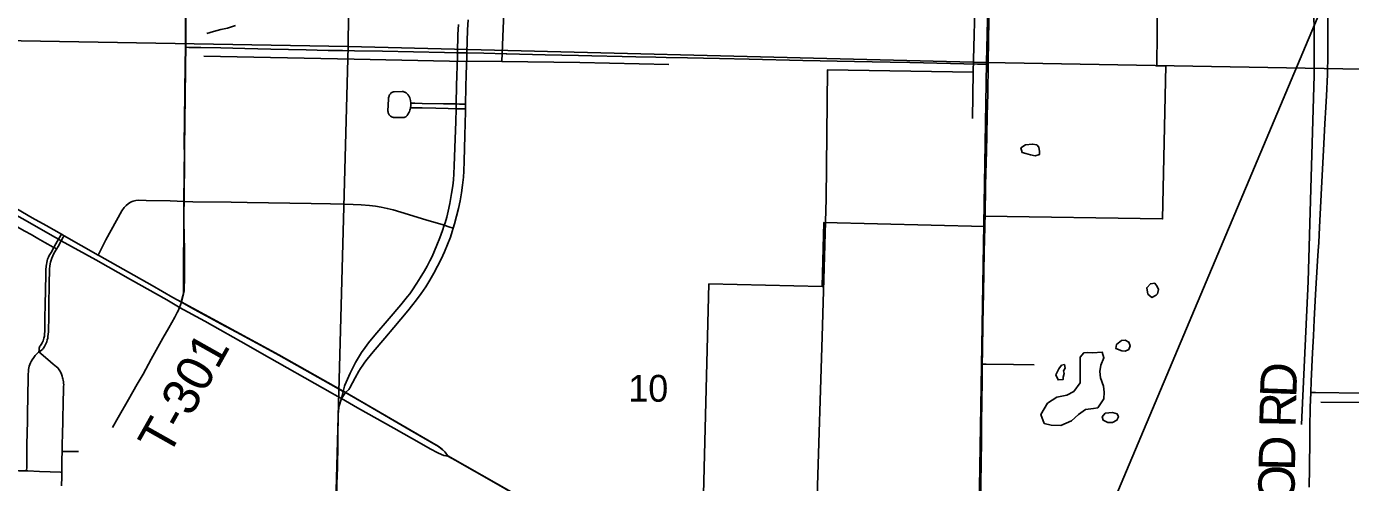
# Model space of a CAD drawing. Extents: x 0 to 34, y 0 to 22.
# Drawn here: x 4.977 to 7.043, y 16.271 to 16.982 of the extents above; entities that cross this region are included whole.
import ezdxf

# ---------------------------------------------------------------- set-up
doc = ezdxf.new("R2010")
doc.units = 0
for name, color, linetype in [('GM_X_City_Street', 7, 'Continuous'), ('GM_X_Corporation', 7, 'Continuous'), ('GM_X_County_Road', 7, 'Continuous'), ('GM_X_Minor_Lake', 7, 'Continuous'), ('GM_X_Minor_River', 7, 'Continuous'), ('GM_X_Rail_Line', 7, 'Continuous'), ('GM_X_Section_Text', 7, 'Continuous'), ('GM_X_Township_Road', 7, 'Continuous'), ('GM_X_Township_Road_Text', 7, 'Continuous'), ('GM_X_US_Route', 7, 'Continuous')]:
    doc.layers.add(name, color=color, linetype=linetype)

msp = doc.modelspace()

# ---------------------------------------------------------------- linework, layer by layer
at = {"layer": 'GM_X_City_Street'}
for points in [[(5.5759, 16.8557), (5.5763, 16.8589), (5.5763, 16.8609), (5.5763, 16.863), (5.5758, 16.8667), (5.5752, 16.8689), (5.5746, 16.8711), (5.5738, 16.8731), (5.5732, 16.8741), (5.5723, 16.8755), (5.5716, 16.8764), (5.5705, 16.8775), (5.5697, 16.8783), (5.5689, 16.8789), (5.5682, 16.8793), (5.5674, 16.8798), (5.5663, 16.8802), (5.5653, 16.8805), (5.5642, 16.8808), (5.563, 16.8809), (5.5503, 16.8807), (5.5491, 16.8805), (5.548, 16.8802), (5.5473, 16.8799), (5.5465, 16.8795), (5.5458, 16.879), (5.5453, 16.8784), (5.5445, 16.8776), (5.5439, 16.8769), (5.5432, 16.8759), (5.5427, 16.875), (5.5423, 16.8739), (5.5419, 16.8728), (5.5416, 16.8713), (5.5414, 16.8694), (5.5407, 16.8502), (5.5408, 16.8491), (5.5411, 16.8479), (5.5415, 16.8468), (5.5421, 16.8456), (5.5426, 16.8448), (5.5431, 16.8442), (5.5438, 16.8433), (5.5447, 16.8425), (5.5457, 16.8418), (5.547, 16.8412), (5.5481, 16.8407), (5.5493, 16.8404), (5.5506, 16.8402), (5.5645, 16.8402), (5.5659, 16.8405), (5.567, 16.8409), (5.5683, 16.8416), (5.5694, 16.8425), (5.5704, 16.8436), (5.5713, 16.8447), (5.5722, 16.846), (5.5729, 16.8473), (5.5735, 16.8486), (5.5742, 16.85), (5.5747, 16.8517), (5.5753, 16.8535), (5.5759, 16.8557)], [(5.5763, 16.863), (5.5825, 16.8629), (5.5941, 16.8625), (5.6273, 16.8618), (5.6471, 16.8615), (5.6522, 16.8614), (5.6618, 16.8613)], [(5.5759, 16.8557), (5.5835, 16.8557), (5.5939, 16.8556), (5.6153, 16.855), (5.6344, 16.8545), (5.6469, 16.8542), (5.6532, 16.8541), (5.6616, 16.8539)], [(5.2224, 16.7092), (5.2364, 16.7091), (5.2958, 16.7083), (5.3207, 16.7079), (5.4206, 16.7062), (5.4509, 16.7056), (5.4727, 16.7051), (5.4865, 16.7045), (5.4991, 16.704), (5.5116, 16.7031), (5.521, 16.702), (5.5303, 16.7005), (5.5395, 16.6985), (5.5487, 16.6963), (5.5607, 16.6928), (5.5997, 16.681), (5.6267, 16.6728), (5.6285, 16.6722), (5.6357, 16.67), (5.6426, 16.6679)]]:
    msp.add_lwpolyline(points, dxfattribs=at)
at = {"layer": 'GM_X_Corporation'}
for points in [[(5.9989, 18.4296), (5.7852, 18.1748), (5.5419, 17.883), (5.4818, 17.8089), (5.2325, 17.5072), (5.2269, 17.3672), (5.225, 16.9563), (5.2221, 16.7098), (5.2215, 16.5659), (5.2182, 16.5527), (5.3703, 16.47), (5.4708, 16.4137), (5.474, 16.4118), (5.6191, 16.3275), (5.6252, 16.3229), (5.6296, 16.3186), (5.634, 16.3123), (5.7366, 16.2544)], [(6.0291, 16.0882), (6.0415, 16.5807), (6.2183, 16.5765), (6.2206, 16.6766), (6.4721, 16.6701), (6.4722, 16.6863), (6.7496, 16.6822), (6.7543, 16.9211), (6.7407, 16.9204), (6.7429, 17.181)]]:
    msp.add_lwpolyline(points, dxfattribs=at)
for points in [[(4.7582, 17.9053), (4.9824, 17.8999), (5.4886, 17.8861), (5.4784, 16.9512), (4.4576, 16.9688), (4.4689, 17.4182), (4.4757, 17.9128)], [(5.4886, 17.8861), (6.497, 17.8754), (6.4745, 16.9262), (5.4784, 16.9512)], [(6.497, 17.8754), (7.515, 17.8763), (7.4991, 16.9078), (6.4745, 16.9262)], [(4.4576, 16.9688), (5.4784, 16.9512), (5.4509, 15.9313), (4.4354, 15.9477)], [(5.4784, 16.9512), (6.4745, 16.9262), (6.4581, 15.916), (5.4509, 15.9313)], [(6.4745, 16.9262), (7.4991, 16.9078), (7.4758, 15.8976), (6.4581, 15.916)]]:
    msp.add_lwpolyline(points, close=True, dxfattribs=at)
at = {"layer": 'GM_X_County_Road'}
for q in [(5.471, 16.4131), (5.4743, 16.4113)]:
    msp.add_line((5.468, 16.4019), q, dxfattribs=at)
for points in [[(6.4774, 16.9235), (6.4774, 16.9274), (6.4782, 16.9927), (6.4787, 17.0176), (6.4793, 17.0455), (6.4797, 17.089), (6.4803, 17.117), (6.4807, 17.1356), (6.4814, 17.1837)], [(5.471, 16.4131), (5.4724, 16.4193), (5.473, 16.4214), (5.4736, 16.4229), (5.4818, 16.4414), (5.4857, 16.4498), (5.4899, 16.4581), (5.4946, 16.4661), (5.4996, 16.4739), (5.5049, 16.4815), (5.5105, 16.4889), (5.5203, 16.5009), (5.5424, 16.527), (5.5605, 16.5484), (5.5711, 16.5609), (5.5746, 16.5655), (5.5781, 16.5702), (5.5857, 16.5819), (5.5911, 16.5904), (5.5979, 16.6013), (5.6017, 16.6083), (5.6062, 16.6167), (5.6095, 16.6236), (5.6135, 16.6324), (5.6171, 16.641), (5.6217, 16.6526), (5.6259, 16.6643), (5.6285, 16.6722), (5.6298, 16.6761), (5.6324, 16.6851), (5.6347, 16.6942), (5.6373, 16.7064), (5.64, 16.7217), (5.6418, 16.734), (5.6428, 16.7433), (5.6435, 16.7526), (5.6441, 16.7651), (5.6449, 16.7931), (5.6464, 16.8344), (5.6469, 16.8542), (5.647, 16.8581), (5.6471, 16.8615), (5.6478, 16.8901), (5.6491, 16.9359), (5.6492, 16.9415), (5.6498, 16.9701), (5.6505, 16.9856)], [(5.6638, 16.9411), (5.6648, 16.9772), (5.6656, 16.9927)], [(5.6616, 16.8539), (5.6618, 16.8613), (5.6623, 16.8871), (5.6627, 16.9078), (5.6635, 16.9337), (5.6638, 16.9411)], [(6.4724, 16.6867), (6.4733, 16.7347), (6.4745, 16.7877), (6.4752, 16.8125), (6.4758, 16.8436), (6.4766, 16.8777), (6.4774, 16.9235)], [(5.6426, 16.6679), (5.6446, 16.6745), (5.6478, 16.6864), (5.6507, 16.6985), (5.6532, 16.7106), (5.6552, 16.7228), (5.6569, 16.7351), (5.6583, 16.7474), (5.6589, 16.7567), (5.6595, 16.7722), (5.6605, 16.8126), (5.6615, 16.8498), (5.6616, 16.8539)], [(6.4723, 16.6695), (6.4722, 16.6768), (6.4724, 16.6857), (6.4724, 16.6867)], [(5.4743, 16.4113), (5.4795, 16.4162), (5.4806, 16.4174), (5.4814, 16.4188), (5.4893, 16.434), (5.4951, 16.4445), (5.4978, 16.449), (5.5013, 16.4542), (5.5046, 16.4589), (5.5081, 16.4634), (5.5177, 16.4749), (5.5357, 16.4962), (5.5496, 16.513), (5.5718, 16.539), (5.5797, 16.5485), (5.5854, 16.5559), (5.5926, 16.5659), (5.5995, 16.5762), (5.606, 16.5868), (5.6122, 16.5975), (5.6181, 16.6084), (5.6236, 16.6195), (5.6287, 16.6308), (5.6335, 16.6422), (5.638, 16.6538), (5.641, 16.6626), (5.6426, 16.6679)], [(6.468, 16.4554), (6.4682, 16.4757), (6.4688, 16.5193), (6.4699, 16.5668), (6.4713, 16.6309), (6.4723, 16.6695)], [(6.4599, 15.8357), (6.4601, 15.8458), (6.4611, 15.889), (6.4616, 15.9206), (6.4623, 15.9482), (6.4625, 15.9792), (6.463, 16.0165), (6.4639, 16.0817), (6.4646, 16.1624), (6.4648, 16.2057), (6.4658, 16.2689), (6.4663, 16.3019), (6.4667, 16.336), (6.4669, 16.3609), (6.4675, 16.4012), (6.4677, 16.4261), (6.468, 16.4554)]]:
    msp.add_lwpolyline(points, dxfattribs=at)
at = {"layer": 'GM_X_Minor_Lake'}
for p, q in [((6.5363, 16.7843), (6.5435, 16.7824)), ((6.7413, 16.5654), (6.7429, 16.5722)), ((6.64, 16.4733), (6.6317, 16.4738)), ((6.6857, 16.4765), (6.691, 16.4761)), ((6.5945, 16.4352), (6.5957, 16.4412)), ((6.6639, 16.3648), (6.6714, 16.3647))]:
    msp.add_line(p, q, dxfattribs=at)
for points in [[(6.5435, 16.7824), (6.5507, 16.7807), (6.5575, 16.7829), (6.5575, 16.7875), (6.5565, 16.794), (6.5531, 16.7978), (6.5467, 16.799), (6.5354, 16.7976), (6.5285, 16.7932), (6.5303, 16.7856), (6.5363, 16.7843)], [(6.7429, 16.5722), (6.7411, 16.5768), (6.7373, 16.5822), (6.7305, 16.5811), (6.7248, 16.5747), (6.7265, 16.5648), (6.7329, 16.5598), (6.7394, 16.5632), (6.7413, 16.5654)], [(6.691, 16.4761), (6.6967, 16.4787), (6.699, 16.484), (6.6969, 16.4901), (6.6909, 16.4928), (6.6852, 16.4925), (6.6776, 16.4865), (6.6763, 16.4801), (6.6857, 16.4765)], [(6.6317, 16.4738), (6.6264, 16.4731), (6.621, 16.4663), (6.6211, 16.4477), (6.6209, 16.4265), (6.6112, 16.413), (6.5998, 16.407), (6.5847, 16.4042), (6.5698, 16.3945), (6.5594, 16.3772), (6.5649, 16.3631), (6.5758, 16.3603), (6.5909, 16.3597), (6.6076, 16.3671), (6.6183, 16.3768), (6.6294, 16.3846), (6.6415, 16.3864), (6.6483, 16.3874), (6.6576, 16.4014), (6.6585, 16.412), (6.6571, 16.4211), (6.6527, 16.4341), (6.6513, 16.4443), (6.6533, 16.4538), (6.658, 16.4655), (6.6551, 16.4743), (6.64, 16.4733)], [(6.5957, 16.4412), (6.595, 16.445), (6.5974, 16.4492), (6.5963, 16.4549), (6.5918, 16.4538), (6.5875, 16.4482), (6.5829, 16.4387), (6.5865, 16.4311), (6.5945, 16.4318), (6.5945, 16.4352)], [(6.6714, 16.3647), (6.6783, 16.3681), (6.6806, 16.3734), (6.6784, 16.3783), (6.6713, 16.3803), (6.6599, 16.3789), (6.6553, 16.3733), (6.6567, 16.368), (6.6639, 16.3648)]]:
    msp.add_lwpolyline(points, dxfattribs=at)
at = {"layer": 'GM_X_Minor_River'}
for points in [[(7.094, 17.6126), (7.1052, 17.5724), (7.1111, 17.5594), (7.114, 17.5469), (7.1138, 17.5306), (7.1129, 17.4953), (7.1066, 17.3549), (6.988, 17.3575), (6.9865, 17.2387), (6.9855, 17.0721), (6.986, 16.9066), (6.981, 16.729), (6.9765, 16.5845), (6.9664, 16.3614)], [(6.4716, 17.5067), (6.4692, 17.3739), (6.4629, 17.1777), (6.4574, 17.048), (6.4541, 16.911), (6.4528, 16.8389)], [(5.7303, 17.2565), (5.7267, 17.1547), (5.7224, 17.031), (5.7181, 16.9278)], [(5.3029, 16.9839), (5.29, 16.9799), (5.2801, 16.9777), (5.2684, 16.9745), (5.2578, 16.9715)], [(5.2535, 16.9359), (5.4881, 16.9315), (5.6369, 16.9285), (5.7181, 16.9278), (5.8401, 16.9263), (5.979, 16.923)], [(6.4541, 16.911), (6.2264, 16.9146), (6.2245, 16.7135), (6.218, 16.498), (6.2106, 16.2498), (6.2, 16.0162)], [(7.9051, 16.3837), (7.6793, 16.3889), (7.4704, 16.3942), (6.9963, 16.3963)]]:
    msp.add_lwpolyline(points, dxfattribs=at)
at = {"layer": 'GM_X_Rail_Line'}
msp.add_lwpolyline([(5.7724, 14.1), (5.9023, 14.4065), (6.108, 14.9012), (7.0925, 17.2371), (7.3462, 17.8422), (7.5826, 18.397), (7.8741, 19.1084), (7.9022, 19.1708), (7.9338, 19.2375), (7.9584, 19.2815), (7.9927, 19.3184), (8.0524, 19.3602), (8.3458, 19.5368)], dxfattribs=at)
at = {"layer": 'GM_X_Township_Road'}
for p, q in [((5.8379, 16.9374), (5.8587, 16.9368)), ((5.8587, 16.9368), (5.9062, 16.9355)), ((5.9062, 16.9355), (5.9277, 16.935)), ((5.2154, 16.5442), (5.2184, 16.5522))]:
    msp.add_line(p, q, dxfattribs=at)
for points in [[(5.2245, 16.95), (5.2247, 16.9811), (5.2252, 17.0216), (5.2257, 17.0589), (5.2258, 17.1025), (5.226, 17.1274), (5.2264, 17.1772), (5.2269, 17.2115), (5.2271, 17.2395), (5.2275, 17.2675), (5.2281, 17.3246)], [(6.9807, 16.4115), (6.9812, 16.4289), (6.9834, 16.473), (6.985, 16.4997), (6.9862, 16.5246), (6.9877, 16.5543), (6.9883, 16.5642), (6.9913, 16.617), (6.9923, 16.6325), (6.9931, 16.6455), (6.9943, 16.6691), (6.9975, 16.73), (7.0004, 16.7896), (7.0028, 16.8305), (7.0043, 16.8566), (7.0053, 16.874), (7.0067, 16.9075), (7.0073, 16.9386), (7.0073, 16.9523), (7.0073, 17.0077)], [(5.2224, 16.7092), (5.2227, 16.7267), (5.2234, 16.7637), (5.223, 16.7798), (5.2228, 16.8006), (5.2233, 16.8348), (5.2236, 16.8815), (5.2244, 16.922), (5.2245, 16.95)], [(5.2245, 16.95), (5.23, 16.9499), (5.2487, 16.9496), (5.2799, 16.9489), (5.3172, 16.9482), (5.3577, 16.9471), (5.4131, 16.9458), (5.4476, 16.9451), (5.4697, 16.9447), (5.4886, 16.9445), (5.5322, 16.9439), (5.6287, 16.942), (5.6474, 16.9415), (5.6492, 16.9415)], [(5.6492, 16.9415), (5.663, 16.9411), (5.6638, 16.9411), (5.6905, 16.9407), (5.7253, 16.9398), (5.7263, 16.9398)], [(5.7263, 16.9398), (5.7858, 16.9383), (5.8379, 16.9374)], [(5.9277, 16.935), (5.9588, 16.9343), (5.9747, 16.9339)], [(5.9747, 16.9339), (6.008, 16.9334), (6.0579, 16.9323), (6.1043, 16.9314), (6.188, 16.9296), (6.2686, 16.9279), (6.2965, 16.9272), (6.3243, 16.9268), (6.3553, 16.9262), (6.4607, 16.9238), (6.4774, 16.9235)], [(5.0884, 16.6258), (5.1006, 16.6495), (5.1256, 16.6947), (5.129, 16.6999), (5.1319, 16.7031), (5.1352, 16.7059), (5.1389, 16.7082), (5.143, 16.7098), (5.1472, 16.7108), (5.1515, 16.7112), (5.1633, 16.7111), (5.2006, 16.7102), (5.2224, 16.7092)], [(5.2184, 16.5522), (5.2217, 16.5653), (5.2222, 16.5675), (5.2226, 16.5697), (5.2228, 16.5717), (5.2233, 16.5908), (5.2234, 16.615), (5.2232, 16.6308), (5.2225, 16.6589), (5.2221, 16.6743), (5.2221, 16.6925), (5.2224, 16.7092)], [(4.9524, 16.6754), (4.962, 16.6699), (4.9739, 16.6632), (4.9837, 16.6578), (4.9944, 16.6516), (5.0053, 16.6455), (5.0181, 16.6383), (5.0193, 16.6376)], [(4.9959, 16.4747), (4.9962, 16.4774), (4.9965, 16.4805), (4.9969, 16.482), (4.9975, 16.4834), (4.9983, 16.4845), (4.9996, 16.4864), (5.0008, 16.4886), (5.0024, 16.4921), (5.0031, 16.4939), (5.0038, 16.4963), (5.0045, 16.4995), (5.0048, 16.5026), (5.0052, 16.5069), (5.0053, 16.5106), (5.0053, 16.5138), (5.0053, 16.5176), (5.0052, 16.5207), (5.0054, 16.5344), (5.0055, 16.5418), (5.0057, 16.5518), (5.006, 16.5679), (5.0062, 16.576), (5.0067, 16.5903), (5.007, 16.6027), (5.0073, 16.6083), (5.0076, 16.6113), (5.0081, 16.6143), (5.0087, 16.6166), (5.0096, 16.6195), (5.0108, 16.6223), (5.0122, 16.6251), (5.0149, 16.6299), (5.0193, 16.6376), (5.0205, 16.6397), (5.0267, 16.6504), (5.0312, 16.6582)], [(5.0309, 16.6481), (5.034, 16.6537), (5.0352, 16.656)], [(4.9959, 16.4747), (4.9978, 16.4758), (4.9998, 16.4772), (5.0013, 16.4785), (5.0021, 16.4793), (5.0029, 16.4805), (5.0047, 16.4833), (5.0062, 16.486), (5.0072, 16.4881), (5.0081, 16.4904), (5.009, 16.4933), (5.0097, 16.4962), (5.0101, 16.4986), (5.0104, 16.5025), (5.0107, 16.5059), (5.0109, 16.509), (5.0111, 16.5133), (5.011, 16.5177), (5.0112, 16.5197), (5.0113, 16.5371), (5.0115, 16.5464), (5.0117, 16.5582), (5.0118, 16.5706), (5.0119, 16.5794), (5.0122, 16.5856), (5.0124, 16.5986), (5.0127, 16.6043), (5.013, 16.6086), (5.0134, 16.6121), (5.014, 16.6149), (5.0149, 16.618), (5.016, 16.6209), (5.0175, 16.6244), (5.0195, 16.6283), (5.0223, 16.6332), (5.0235, 16.6352)], [(5.0193, 16.6376), (5.0217, 16.6363), (5.0235, 16.6352)], [(5.0235, 16.6352), (5.0258, 16.6391), (5.0309, 16.6481)], [(5.1816, 16.482), (5.1896, 16.4961), (5.1987, 16.5125), (5.2079, 16.5288), (5.2119, 16.5362), (5.2131, 16.5387), (5.2142, 16.5412), (5.2154, 16.5442)], [(4.9767, 16.289), (4.9769, 16.2955), (4.977, 16.2997), (4.9771, 16.3078), (4.9771, 16.3164), (4.9772, 16.322), (4.9773, 16.3344), (4.9776, 16.3443), (4.9778, 16.3542), (4.9779, 16.3609), (4.978, 16.371), (4.9782, 16.3818), (4.9784, 16.3883), (4.9785, 16.3953), (4.9786, 16.4007), (4.9787, 16.4077), (4.9789, 16.4155), (4.9791, 16.4254), (4.9792, 16.433), (4.9792, 16.4399), (4.9795, 16.4442), (4.9798, 16.4473), (4.9803, 16.4498), (4.9809, 16.4522), (4.9819, 16.4551), (4.9829, 16.4574), (4.984, 16.4596), (4.9856, 16.4623), (4.9881, 16.4659), (4.9902, 16.4689), (4.9919, 16.4706), (4.9959, 16.4747)], [(5.0321, 16.3191), (5.0322, 16.3219), (5.0324, 16.3289), (5.0328, 16.3486), (5.0331, 16.3644), (5.0334, 16.3772), (5.0337, 16.3884), (5.034, 16.4012), (5.0342, 16.411), (5.0345, 16.4212), (5.0346, 16.4233), (5.0345, 16.4258), (5.0342, 16.4278), (5.0338, 16.4307), (5.0335, 16.4326), (5.033, 16.4345), (5.0322, 16.4369), (5.031, 16.4401), (5.0296, 16.4434), (5.0288, 16.4451), (5.0278, 16.4468), (5.0266, 16.4483), (5.0253, 16.4498), (5.0234, 16.4515), (5.0181, 16.4558), (5.01, 16.4626), (4.9959, 16.4747)], [(5.1109, 16.3566), (5.1197, 16.3723), (5.1357, 16.4006), (5.1494, 16.4246), (5.1584, 16.4402), (5.1712, 16.4635), (5.1816, 16.482)], [(6.468, 16.4554), (6.474, 16.4554), (6.5166, 16.4549), (6.5489, 16.4543)], [(6.9782, 16.2636), (6.9785, 16.2933), (6.9792, 16.3383), (6.9794, 16.3512), (6.9795, 16.3568), (6.98, 16.3879), (6.9807, 16.4115)], [(6.9807, 16.4115), (6.9883, 16.4114), (7.0616, 16.4104), (7.1474, 16.4098), (7.2161, 16.4092), (7.2571, 16.4093), (7.3355, 16.4101), (7.3641, 16.4105), (7.4261, 16.4113), (7.4732, 16.4118), (7.4925, 16.4118), (7.5142, 16.4114), (7.5583, 16.4099), (7.6882, 16.4061), (7.741, 16.4042), (7.8256, 16.4018), (7.9293, 16.3982), (7.9939, 16.3959), (7.9972, 16.3958)], [(5.4589, 16.1391), (5.4593, 16.1587), (5.4598, 16.1991), (5.4602, 16.2227), (5.461, 16.2687), (5.4617, 16.2942), (5.4621, 16.3079), (5.4623, 16.3178), (5.4625, 16.334), (5.4626, 16.3496), (5.4629, 16.3682), (5.4631, 16.3769), (5.4633, 16.383), (5.4638, 16.3872), (5.4646, 16.3905), (5.468, 16.4019)], [(5.0317, 16.2868), (5.0318, 16.2942), (5.0318, 16.3041), (5.0319, 16.3103), (5.032, 16.3153), (5.0321, 16.3191)], [(5.0321, 16.3191), (5.0333, 16.3191), (5.0384, 16.3191), (5.0428, 16.3191), (5.0477, 16.3191), (5.0515, 16.3191), (5.0577, 16.3191)], [(4.8878, 16.2633), (4.8952, 16.2763), (4.8975, 16.2799), (4.8989, 16.2819), (4.9005, 16.2837), (4.9022, 16.2854), (4.9041, 16.2869), (4.9061, 16.2881), (4.9082, 16.2892), (4.9105, 16.2901), (4.9128, 16.2907), (4.9145, 16.291), (4.9169, 16.2913), (4.92, 16.2913), (4.9305, 16.291), (4.9417, 16.2905), (4.9448, 16.2904), (4.9472, 16.2903), (4.9541, 16.29), (4.9646, 16.2894), (4.9767, 16.289)], [(4.9767, 16.289), (4.9789, 16.289), (4.9969, 16.2883), (5.0137, 16.2875), (5.0299, 16.2869), (5.0317, 16.2868)], [(5.0312, 16.2659), (5.0313, 16.271), (5.0315, 16.2746), (5.0316, 16.2793), (5.0317, 16.2829), (5.0317, 16.2868)]]:
    msp.add_lwpolyline(points, dxfattribs=at)
at = {"layer": 'GM_X_US_Route'}
for p, q in [((5.0312, 16.6582), (5.0352, 16.656)), ((5.0352, 16.656), (5.0884, 16.6258)), ((5.471, 16.4131), (5.4743, 16.4113))]:
    msp.add_line(p, q, dxfattribs=at)
for points in [[(4.9032, 16.7306), (4.9245, 16.7187), (4.9613, 16.6979), (4.9856, 16.684), (5.0072, 16.6718), (5.0312, 16.6582)], [(4.952, 16.6927), (4.9698, 16.6826), (5.0218, 16.6532), (5.0267, 16.6504), (5.0309, 16.6481), (5.0847, 16.6182), (5.139, 16.5878), (5.1956, 16.5561), (5.2112, 16.5467), (5.2154, 16.5442)], [(5.0884, 16.6258), (5.0906, 16.6246), (5.1729, 16.5782), (5.2051, 16.5598), (5.2184, 16.5522)], [(5.2184, 16.5522), (5.2332, 16.544), (5.2807, 16.5181), (5.3113, 16.5016), (5.3486, 16.4817), (5.3705, 16.4694), (5.4517, 16.4241), (5.471, 16.4131)], [(5.2154, 16.5442), (5.2547, 16.5226), (5.3228, 16.4842)], [(5.3228, 16.4842), (5.3402, 16.4743), (5.4541, 16.4098)], [(5.4541, 16.4098), (5.4576, 16.4078), (5.468, 16.4019), (5.4933, 16.3876), (5.55, 16.3555)], [(5.4743, 16.4113), (5.477, 16.4097), (5.5039, 16.3941), (5.5754, 16.3526), (5.6193, 16.327), (5.6254, 16.3224), (5.6298, 16.3181), (5.6343, 16.3118)], [(5.55, 16.3555), (5.5928, 16.3312), (5.6067, 16.3233), (5.6186, 16.3171), (5.6241, 16.3145), (5.628, 16.313), (5.631, 16.3123), (5.6343, 16.3118)], [(5.6343, 16.3118), (5.6457, 16.3056), (5.7058, 16.2716), (5.7368, 16.2539)]]:
    msp.add_lwpolyline(points, dxfattribs=at)

# ---------------------------------------------------------------- texts
at = {"layer": 'GM_X_Section_Text'}
msp.add_text('10', height=0.04186, rotation=0, dxfattribs=at).set_placement((5.9158, 16.397))
at = {"layer": 'GM_X_Township_Road_Text'}
for s, height, rotation, p in [('T-301', 0.05682, 60.6064, (5.1977, 16.3096)), ('D', 0.0568, 87.9158, (6.9581, 16.4027)), ('R', 0.0568, 88.9696, (6.9572, 16.3563)), ('D', 0.0568, 89.0273, (6.9561, 16.2889)), ('O', 0.0568, 89.0297, (6.9552, 16.2389))]:
    msp.add_text(s, height=height, rotation=rotation, dxfattribs=at).set_placement(p)

doc.saveas('drawing.dxf')
